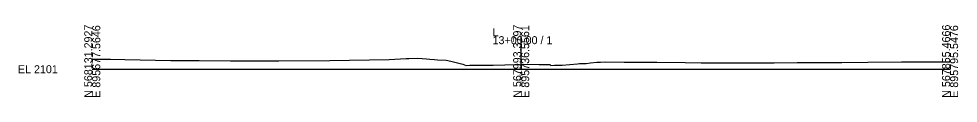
# Model space of a CAD drawing. Extents: x -26 to 1603, y -10 to 13527.
# Drawn here: x -25.7 to 302.8, y -9.7 to 15.4 of the extents above; entities that cross this region are included whole.
import ezdxf

# ---------------------------------------------------------------- set-up
doc = ezdxf.new("R2010")
doc.units = 0
for name, color, linetype in [('Exist XS Center Line Elevation Label', 7, 'Continuous'), ('Exist XS Ground Line', 7, 'Continuous'), ('Old_Level_63', 7, 'Continuous')]:
    doc.layers.add(name, color=color, linetype=linetype)

msp = doc.modelspace()

# ---------------------------------------------------------------- linework, layer by layer
at = {"layer": 'Exist XS Ground Line'}
for p, q in [((0, 3.53), (1.6, 3.56)), ((1.6, 3.56), (3.59, 3.56)), ((3.59, 3.56), (6.4, 3.56)), ((6.4, 3.56), (11.45, 3.42)), ((11.45, 3.42), (27.44, 3.08)), ((83.1, 3.07), (103.8, 3.39)), ((103.8, 3.39), (109.73, 3.76)), ((109.73, 3.76), (110.73, 3.78)), ((110.73, 3.78), (113.88, 3.85)), ((113.88, 3.85), (116.91, 3.62)), ((116.91, 3.62), (118.06, 3.52)), ((118.06, 3.52), (119.66, 3.37)), ((119.66, 3.37), (120.71, 3.33)), ((120.71, 3.33), (123.81, 3.11)), ((27.44, 3.08), (37.41, 3.03)), ((37.41, 3.03), (48.29, 2.88)), ((48.29, 2.88), (59.37, 2.9)), ((59.37, 2.9), (63.35, 2.98)), ((63.35, 2.98), (65.25, 2.99)), ((65.25, 2.99), (83.1, 3.07)), ((123.81, 3.11), (125.43, 2.82)), ((125.43, 2.82), (129.55, 1.72)), ((129.55, 1.72), (130.73, 1.34)), ((130.73, 1.34), (131.99, 1.38)), ((131.99, 1.38), (140.19, 1.47)), ((140.19, 1.47), (144.3, 1.57)), ((144.3, 1.57), (150, 1.69)), ((150, 1.69), (150.84, 1.71)), ((150.84, 1.71), (156.3, 1.7)), ((156.3, 1.7), (160.01, 1.67)), ((160.01, 1.67), (160.34, 1.35)), ((160.34, 1.35), (161.69, 1.4)), ((161.69, 1.4), (164.34, 1.46)), ((164.34, 1.46), (169.71, 1.93)), ((169.71, 1.93), (170.34, 1.97)), ((170.34, 1.97), (172.76, 2.02)), ((172.76, 2.02), (174.24, 2.29)), ((174.24, 2.29), (176.45, 2.44)), ((176.45, 2.44), (176.83, 2.45)), ((176.83, 2.45), (177.73, 2.49)), ((177.73, 2.49), (179.63, 2.54)), ((179.63, 2.54), (186.01, 2.44)), ((186.01, 2.44), (186.94, 2.45)), ((186.94, 2.45), (191.53, 2.44)), ((191.53, 2.44), (197.46, 2.41)), ((197.46, 2.41), (207.32, 2.3)), ((207.32, 2.3), (212.96, 2.29)), ((212.96, 2.29), (214.12, 2.29)), ((214.12, 2.29), (217.15, 2.27)), ((217.15, 2.27), (231.39, 2.28)), ((231.39, 2.28), (234.26, 2.2)), ((234.26, 2.2), (237.27, 2.23)), ((237.27, 2.23), (238.53, 2.29)), ((238.53, 2.29), (246.56, 2.4)), ((246.56, 2.4), (253.22, 2.39)), ((253.22, 2.39), (262.18, 2.37)), ((262.18, 2.37), (271.28, 2.44)), ((271.28, 2.44), (282.97, 2.56)), ((282.97, 2.56), (289.11, 2.57)), ((289.11, 2.57), (291.91, 2.54)), ((291.91, 2.54), (295.86, 2.54)), ((295.86, 2.54), (300, 2.59))]:
    msp.add_line(p, q, dxfattribs=at)
at = {"layer": 'Old_Level_63'}
for p, q in [((150, 0), (150, 11.56)), ((0, 0), (150, 0)), ((150, 0), (300, 0))]:
    msp.add_line(p, q, dxfattribs=at)

# ---------------------------------------------------------------- texts
at = {"layer": 'Exist XS Center Line Elevation Label'}
msp.add_text('2102.69', height=1, rotation=90, dxfattribs=at).set_placement((150.5, -5.86))
at = {"layer": 'Old_Level_63'}
for s, p in [('N 568131.2927', (0, -10)), ('E 895677.5646', (2.8, -10)), ('N 567993.3797', (150, -10)), ('E 895736.5561', (152.8, -10)), ('N 567855.4666', (300, -10)), ('E 895795.5476', (302.8, -10))]:
    msp.add_text(s, height=2.8, rotation=90, dxfattribs=at).set_placement(p)
for s, p in [('L', (140, 11.56)), ('13+00.00 / 1', (140, 8.76)), ('EL 2101', (-26, -1.4))]:
    msp.add_text(s, height=2.8, dxfattribs=at).set_placement(p)

doc.saveas('drawing.dxf')
